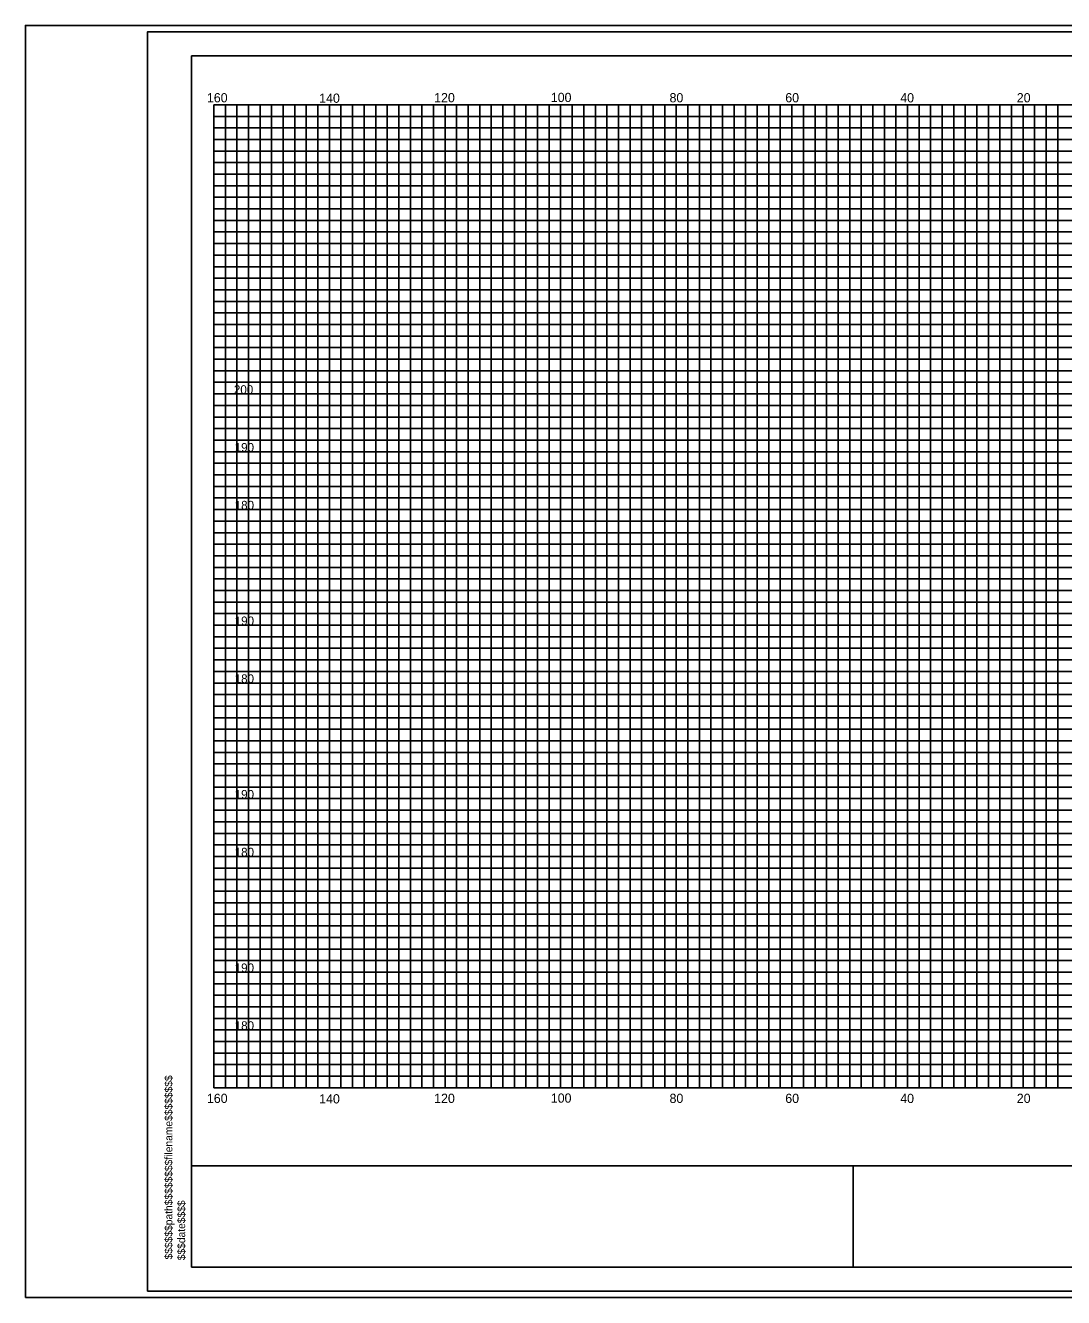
# Model space of a CAD drawing. Extents: x 967 to 1326, y 964 to 1184.
# Drawn here: x 967.4 to 1147, y 963.7 to 1183.7 of the extents above; entities that cross this region are included whole.
import ezdxf

# ---------------------------------------------------------------- set-up
doc = ezdxf.new("R2010")
doc.units = 0
for name, color, linetype in [('Default', 7, 'Continuous'), ('RD_SHT_Bndy', 7, 'Continuous'), ('RD_SHT_IplotShp', 7, 'Continuous'), ('RD_SHT_MjGrid', 7, 'Continuous'), ('RD_SHT_MnGrid', 7, 'Continuous'), ('RD_SHT_TX', 7, 'Continuous'), ('RD_Sketch1', 7, 'Continuous')]:
    doc.layers.add(name, color=color, linetype=linetype)

msp = doc.modelspace()

# ---------------------------------------------------------------- linework, layer by layer
at = {"layer": 'RD_SHT_Bndy'}
for p, q in [((996.11, 968.98), (996.11, 1178.46)), ((996.11, 1178.46), (1323.89, 1178.46)), ((996.11, 986.49), (1323.89, 986.49)), ((1110.59, 968.98), (1110.59, 986.56)), ((1323.89, 968.98), (996.11, 968.98))]:
    msp.add_line(p, q, dxfattribs=at)
at = {"layer": 'RD_SHT_IplotShp'}
for points in [[(967.41, 963.72), (1326.28, 963.72), (1326.28, 1183.72), (967.41, 1183.72)], [(988.52, 964.84), (1326.28, 964.84), (1326.28, 1182.6), (988.52, 1182.6)]]:
    msp.add_lwpolyline(points, close=True, dxfattribs=at)
at = {"layer": 'RD_SHT_MjGrid'}
for p, q in [((1000, 1170), (1320, 1170)), ((1000, 1000), (1000, 1170)), ((1010, 1000), (1010, 1170)), ((1020, 1000), (1020, 1170)), ((1030, 1000), (1030, 1170)), ((1040, 1000), (1040, 1170)), ((1050, 1000), (1050, 1170)), ((1060, 1000), (1060, 1170)), ((1070, 1000), (1070, 1170)), ((1080, 1000), (1080, 1170)), ((1090, 1000), (1090, 1170)), ((1100, 1000), (1100, 1170)), ((1110, 1000), (1110, 1170)), ((1120, 1000), (1120, 1170)), ((1130, 1000), (1130, 1170)), ((1140, 1000), (1140, 1170)), ((1000, 1160), (1320, 1160)), ((1000, 1150), (1320, 1150)), ((1000, 1140), (1320, 1140)), ((1000, 1130), (1320, 1130)), ((1000, 1120), (1320, 1120)), ((1000, 1110), (1320, 1110)), ((1000, 1100), (1320, 1100)), ((1000, 1090), (1320, 1090)), ((1000, 1080), (1320, 1080)), ((1000, 1070), (1320, 1070)), ((1000, 1060), (1320, 1060)), ((1000, 1050), (1320, 1050)), ((1000, 1040), (1320, 1040)), ((1000, 1030), (1320, 1030)), ((1000, 1020), (1320, 1020)), ((1000, 1010), (1320, 1010)), ((1000, 1000), (1320, 1000))]:
    msp.add_line(p, q, dxfattribs=at)
at = {"layer": 'RD_SHT_MnGrid'}
for p, q in [((1002, 1000), (1002, 1170)), ((1004, 1000), (1004, 1170)), ((1006, 1000), (1006, 1170)), ((1008, 1000), (1008, 1170)), ((1012, 1000), (1012, 1170)), ((1014, 1000), (1014, 1170)), ((1016, 1000), (1016, 1170)), ((1018, 1000), (1018, 1170)), ((1022, 1000), (1022, 1170)), ((1024, 1000), (1024, 1170)), ((1026, 1000), (1026, 1170)), ((1028, 1000), (1028, 1170)), ((1032, 1000), (1032, 1170)), ((1034, 1000), (1034, 1170)), ((1036, 1000), (1036, 1170)), ((1038, 1000), (1038, 1170)), ((1042, 1000), (1042, 1170)), ((1044, 1000), (1044, 1170)), ((1046, 1000), (1046, 1170)), ((1048, 1000), (1048, 1170)), ((1052, 1000), (1052, 1170)), ((1054, 1000), (1054, 1170)), ((1056, 1000), (1056, 1170)), ((1058, 1000), (1058, 1170)), ((1062, 1000), (1062, 1170)), ((1064, 1000), (1064, 1170)), ((1066, 1000), (1066, 1170)), ((1068, 1000), (1068, 1170)), ((1072, 1000), (1072, 1170)), ((1074, 1000), (1074, 1170)), ((1076, 1000), (1076, 1170)), ((1078, 1000), (1078, 1170)), ((1082, 1000), (1082, 1170)), ((1084, 1000), (1084, 1170)), ((1086, 1000), (1086, 1170)), ((1088, 1000), (1088, 1170)), ((1092, 1000), (1092, 1170)), ((1094, 1000), (1094, 1170)), ((1096, 1000), (1096, 1170)), ((1098, 1000), (1098, 1170)), ((1102, 1000), (1102, 1170)), ((1104, 1000), (1104, 1170)), ((1106, 1000), (1106, 1170)), ((1108, 1000), (1108, 1170)), ((1112, 1000), (1112, 1170)), ((1114, 1000), (1114, 1170)), ((1116, 1000), (1116, 1170)), ((1118, 1000), (1118, 1170)), ((1122, 1000), (1122, 1170)), ((1124, 1000), (1124, 1170)), ((1126, 1000), (1126, 1170)), ((1128, 1000), (1128, 1170)), ((1132, 1000), (1132, 1170)), ((1134, 1000), (1134, 1170)), ((1136, 1000), (1136, 1170)), ((1138, 1000), (1138, 1170)), ((1142, 1000), (1142, 1170)), ((1144, 1000), (1144, 1170)), ((1146, 1000), (1146, 1170)), ((1000, 1168), (1320, 1168)), ((1000, 1166), (1320, 1166)), ((1000, 1164), (1320, 1164)), ((1000, 1162), (1320, 1162)), ((1000, 1158), (1320, 1158)), ((1000, 1156), (1320, 1156)), ((1000, 1154), (1320, 1154)), ((1000, 1152), (1320, 1152)), ((1000, 1148), (1320, 1148)), ((1000, 1146), (1320, 1146)), ((1000, 1144), (1320, 1144)), ((1000, 1142), (1320, 1142)), ((1000, 1138), (1320, 1138)), ((1000, 1136), (1320, 1136)), ((1000, 1134), (1320, 1134)), ((1000, 1132), (1320, 1132)), ((1000, 1128), (1320, 1128)), ((1000, 1126), (1320, 1126)), ((1000, 1124), (1320, 1124)), ((1000, 1122), (1320, 1122)), ((1000, 1118), (1320, 1118)), ((1000, 1116), (1320, 1116)), ((1000, 1114), (1320, 1114)), ((1000, 1112), (1320, 1112)), ((1000, 1108), (1320, 1108)), ((1000, 1106), (1320, 1106)), ((1000, 1104), (1320, 1104)), ((1000, 1102), (1320, 1102)), ((1000, 1098), (1320, 1098)), ((1000, 1096), (1320, 1096)), ((1000, 1094), (1320, 1094)), ((1000, 1092), (1320, 1092)), ((1000, 1088), (1320, 1088)), ((1000, 1086), (1320, 1086)), ((1000, 1084), (1320, 1084)), ((1000, 1082), (1320, 1082)), ((1000, 1078), (1320, 1078)), ((1000, 1076), (1320, 1076)), ((1000, 1074), (1320, 1074)), ((1000, 1072), (1320, 1072)), ((1000, 1068), (1320, 1068)), ((1000, 1066), (1320, 1066)), ((1000, 1064), (1320, 1064)), ((1000, 1062), (1320, 1062)), ((1000, 1058), (1320, 1058)), ((1000, 1056), (1320, 1056)), ((1000, 1054), (1320, 1054)), ((1000, 1052), (1320, 1052)), ((1000, 1048), (1320, 1048)), ((1000, 1046), (1320, 1046)), ((1000, 1044), (1320, 1044)), ((1000, 1042), (1320, 1042)), ((1000, 1038), (1320, 1038)), ((1000, 1036), (1320, 1036)), ((1000, 1034), (1320, 1034)), ((1000, 1032), (1320, 1032)), ((1000, 1028), (1320, 1028)), ((1000, 1026), (1320, 1026)), ((1000, 1024), (1320, 1024)), ((1000, 1022), (1320, 1022)), ((1000, 1018), (1320, 1018)), ((1000, 1016), (1320, 1016)), ((1000, 1014), (1320, 1014)), ((1000, 1012), (1320, 1012)), ((1000, 1008), (1320, 1008)), ((1000, 1006), (1320, 1006)), ((1000, 1004), (1320, 1004)), ((1000, 1002), (1320, 1002))]:
    msp.add_line(p, q, dxfattribs=at)
at = {"layer": 'RD_Sketch1'}
msp.add_lwpolyline([(967.41, 963.72), (1326.28, 963.72), (1326.28, 1183.72), (967.41, 1183.72)], close=True, dxfattribs=at)

# ---------------------------------------------------------------- texts
at = {"layer": 'Default'}
for s, p in [('200', (1003.47, 1120)), ('190', (1003.61, 1110)), ('180', (1003.61, 1100)), ('190', (1003.61, 1080)), ('180', (1003.61, 1070)), ('190', (1003.61, 1050)), ('180', (1003.61, 1040)), ('190', (1003.61, 1020)), ('180', (1003.61, 1010))]:
    msp.add_text(s, height=1.5, dxfattribs=at).set_placement(p)
for s, p in [('$$$$$$path$$$$$$$$filename$$$$$$$$', (992.83, 970.31)), ('$$$date$$$$', (995.04, 970.17))]:
    msp.add_text(s, height=1.3258, rotation=90, dxfattribs=at).set_placement(p)
at = {"layer": 'RD_SHT_TX'}
for s, p in [('160', (998.81, 1170.42)), ('140', (1018.23, 1170.34)), ('120', (1038.12, 1170.43)), ('100', (1058.3, 1170.47)), ('80', (1078.84, 1170.42)), ('60', (1098.86, 1170.42)), ('40', (1118.75, 1170.41)), ('20', (1138.91, 1170.42)), ('160', (998.81, 997.37)), ('140', (1018.23, 997.29)), ('120', (1038.12, 997.38)), ('100', (1058.3, 997.42)), ('80', (1078.84, 997.37)), ('60', (1098.86, 997.37)), ('40', (1118.75, 997.36)), ('20', (1138.91, 997.37))]:
    msp.add_text(s, height=1.6, dxfattribs=at).set_placement(p)

doc.saveas('drawing.dxf')
